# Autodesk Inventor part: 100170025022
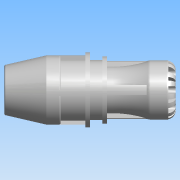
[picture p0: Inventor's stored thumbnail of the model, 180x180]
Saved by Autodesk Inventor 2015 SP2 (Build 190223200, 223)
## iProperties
Created: 2016-12
Part Number: 100170025022
Material: PVC-Piping
Description: PLASSON UNIVERSAL COUPLING 19-22X25 SERIES 1
Document SubType Name: Modeling
Designer: KIM
Density: 1.4 g/cm^3
Appearance: Smooth - White
Author: KIM
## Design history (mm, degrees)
derived "10017.ipt"
feature "Solid1::10017.ipt"
tag "TaggingFeature1"
body "Solid1"
other parameters: "d15" = 22, "d16" = 21.56, "d20" = 46.74, "d21" = 80 deg, "d22" = 18.57143, "d23" = 0, "d25" = 360 deg, "d48" = 1.25, "d52" = 0.57, "d72" = 25, "d73" = 48, "d74" = 2.5, "d79" = 31.25, "d80" = 20.16, "d81" = 77 deg, "d83" = 65, "d84" = 47, "d85" = 3.2, "d86" = 57, "d87" = 52.44, "d88" = 45, "d89" = 9.4, "d90" = 45.6, "d91" = 36, "d93" = 1.3, "d96" = 5.5, "d97" = 5.5, "d98" = 0, "d100" = 360 deg, "d103" = 0.5, "d104" = 0.5, "d105" = 8 deg, "d106" = 8 deg, "d108" = 0, "d110" = 360 deg, "d112" = 7.5, "d113" = 3.75, "d115" = 38.4, "d116" = 0, "d118" = 360 deg, "d120" = 5.7, "d121" = 0.57, "d_" = 25, "E_" = 57, "l_" = 48, "d_1" = 22, "l_1" = 47, "d66" = 76, "d68" = 41, "d69" = 45, "d70" = 20.955, "d71" = 13, "d92" = 6.875, "d94" = 45, "d102" = 31.25
